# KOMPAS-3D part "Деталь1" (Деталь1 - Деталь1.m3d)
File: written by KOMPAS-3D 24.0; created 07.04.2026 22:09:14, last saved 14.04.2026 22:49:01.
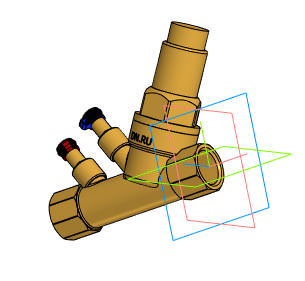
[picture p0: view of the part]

Document properties: Автор: tyuri; Полное имя файла: D:\Аутсорс\VB0000P-T Клапан балансировочный статический DN.ru\DN15\Исходные файлы\Деталь1 - Деталь1.m3d

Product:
- Body: Твердое тело1  | qty 1
    Масса: 0.341211
- Part/product: Деталь1
    Масса: 0.341211
    additional columns: Типовые

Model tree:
1. Твердое тело1  (labels: Твердое тело1)
2. Изменить положение граней:1  (labels: Грань.Твердое тело1)
     Расстояние = 1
